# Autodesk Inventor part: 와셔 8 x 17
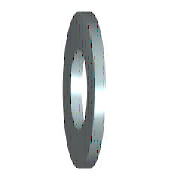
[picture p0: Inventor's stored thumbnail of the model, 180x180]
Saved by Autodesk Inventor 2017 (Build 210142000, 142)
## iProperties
IsCustomPart: 1
Created: 2012-02
Part Number: 와셔 8 x 17
Material: 강철, 연강
Description: 평면 와셔
Document SubType Name: Modeling
Standard: KS B 1326
Designer: mduedu
Standards Organization: KS
Language: ko-KR
Size Designation: 8x17
Categories: <MemberInstance><Categories><Category DisplayName="조임쇠" InternalName="e4da775c-781d-43d5-af7c-5136215cf5a6" Mnemonic="FSTN"><Category DisplayName="와셔" InternalN
Density: 7.86 g/cm^3
Mass: 2.15757 g
Surface Area: 4.70799 cm^2
Volume: 0.2745 cm^3
Appearance: 주황색
Author: mduedu
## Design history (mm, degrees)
sketch "스케치"
  geometry: C1 r 8.5 at (0, 0); C2 r 4.2 at (0, 0); 1 further point
  constraints: 2 centre point, 2 coincident
  dimensions: "d0" = 8.4 diameter of C2 (= SD1); "d1" = 17 diameter of C1 (= SD2)
extrude "본체" new body sketch "스케치" distance "d2" = 1.6 (= SD); taper "d3" = 0 deg
workaxis "Work Axis1"
workplane "Work Plane1"
body "Solid1"
other parameters: "SD1" = 8.4 [user parameter; used in 1 equation term], "SD2" = 17 [user parameter; used in 1 equation term], "SD" = 1.6 [user parameter; used in 1 equation term], "d4" = 0, "d5" = 0, "d6" = 0, "d7" = 0, "NND" = 8 [user parameter]
